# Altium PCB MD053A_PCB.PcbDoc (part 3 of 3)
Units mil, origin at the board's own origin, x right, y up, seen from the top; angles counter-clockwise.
Board outline 3650 x 5180 mil, 4 copper layers (Top Layer, GND Layer, Power Layer, Bottom Layer), stack 58.4 mil thick; 251 components, 138 nets, 532 pads, 1017 vias.
Unrouted connection lines stored in the file: 42.
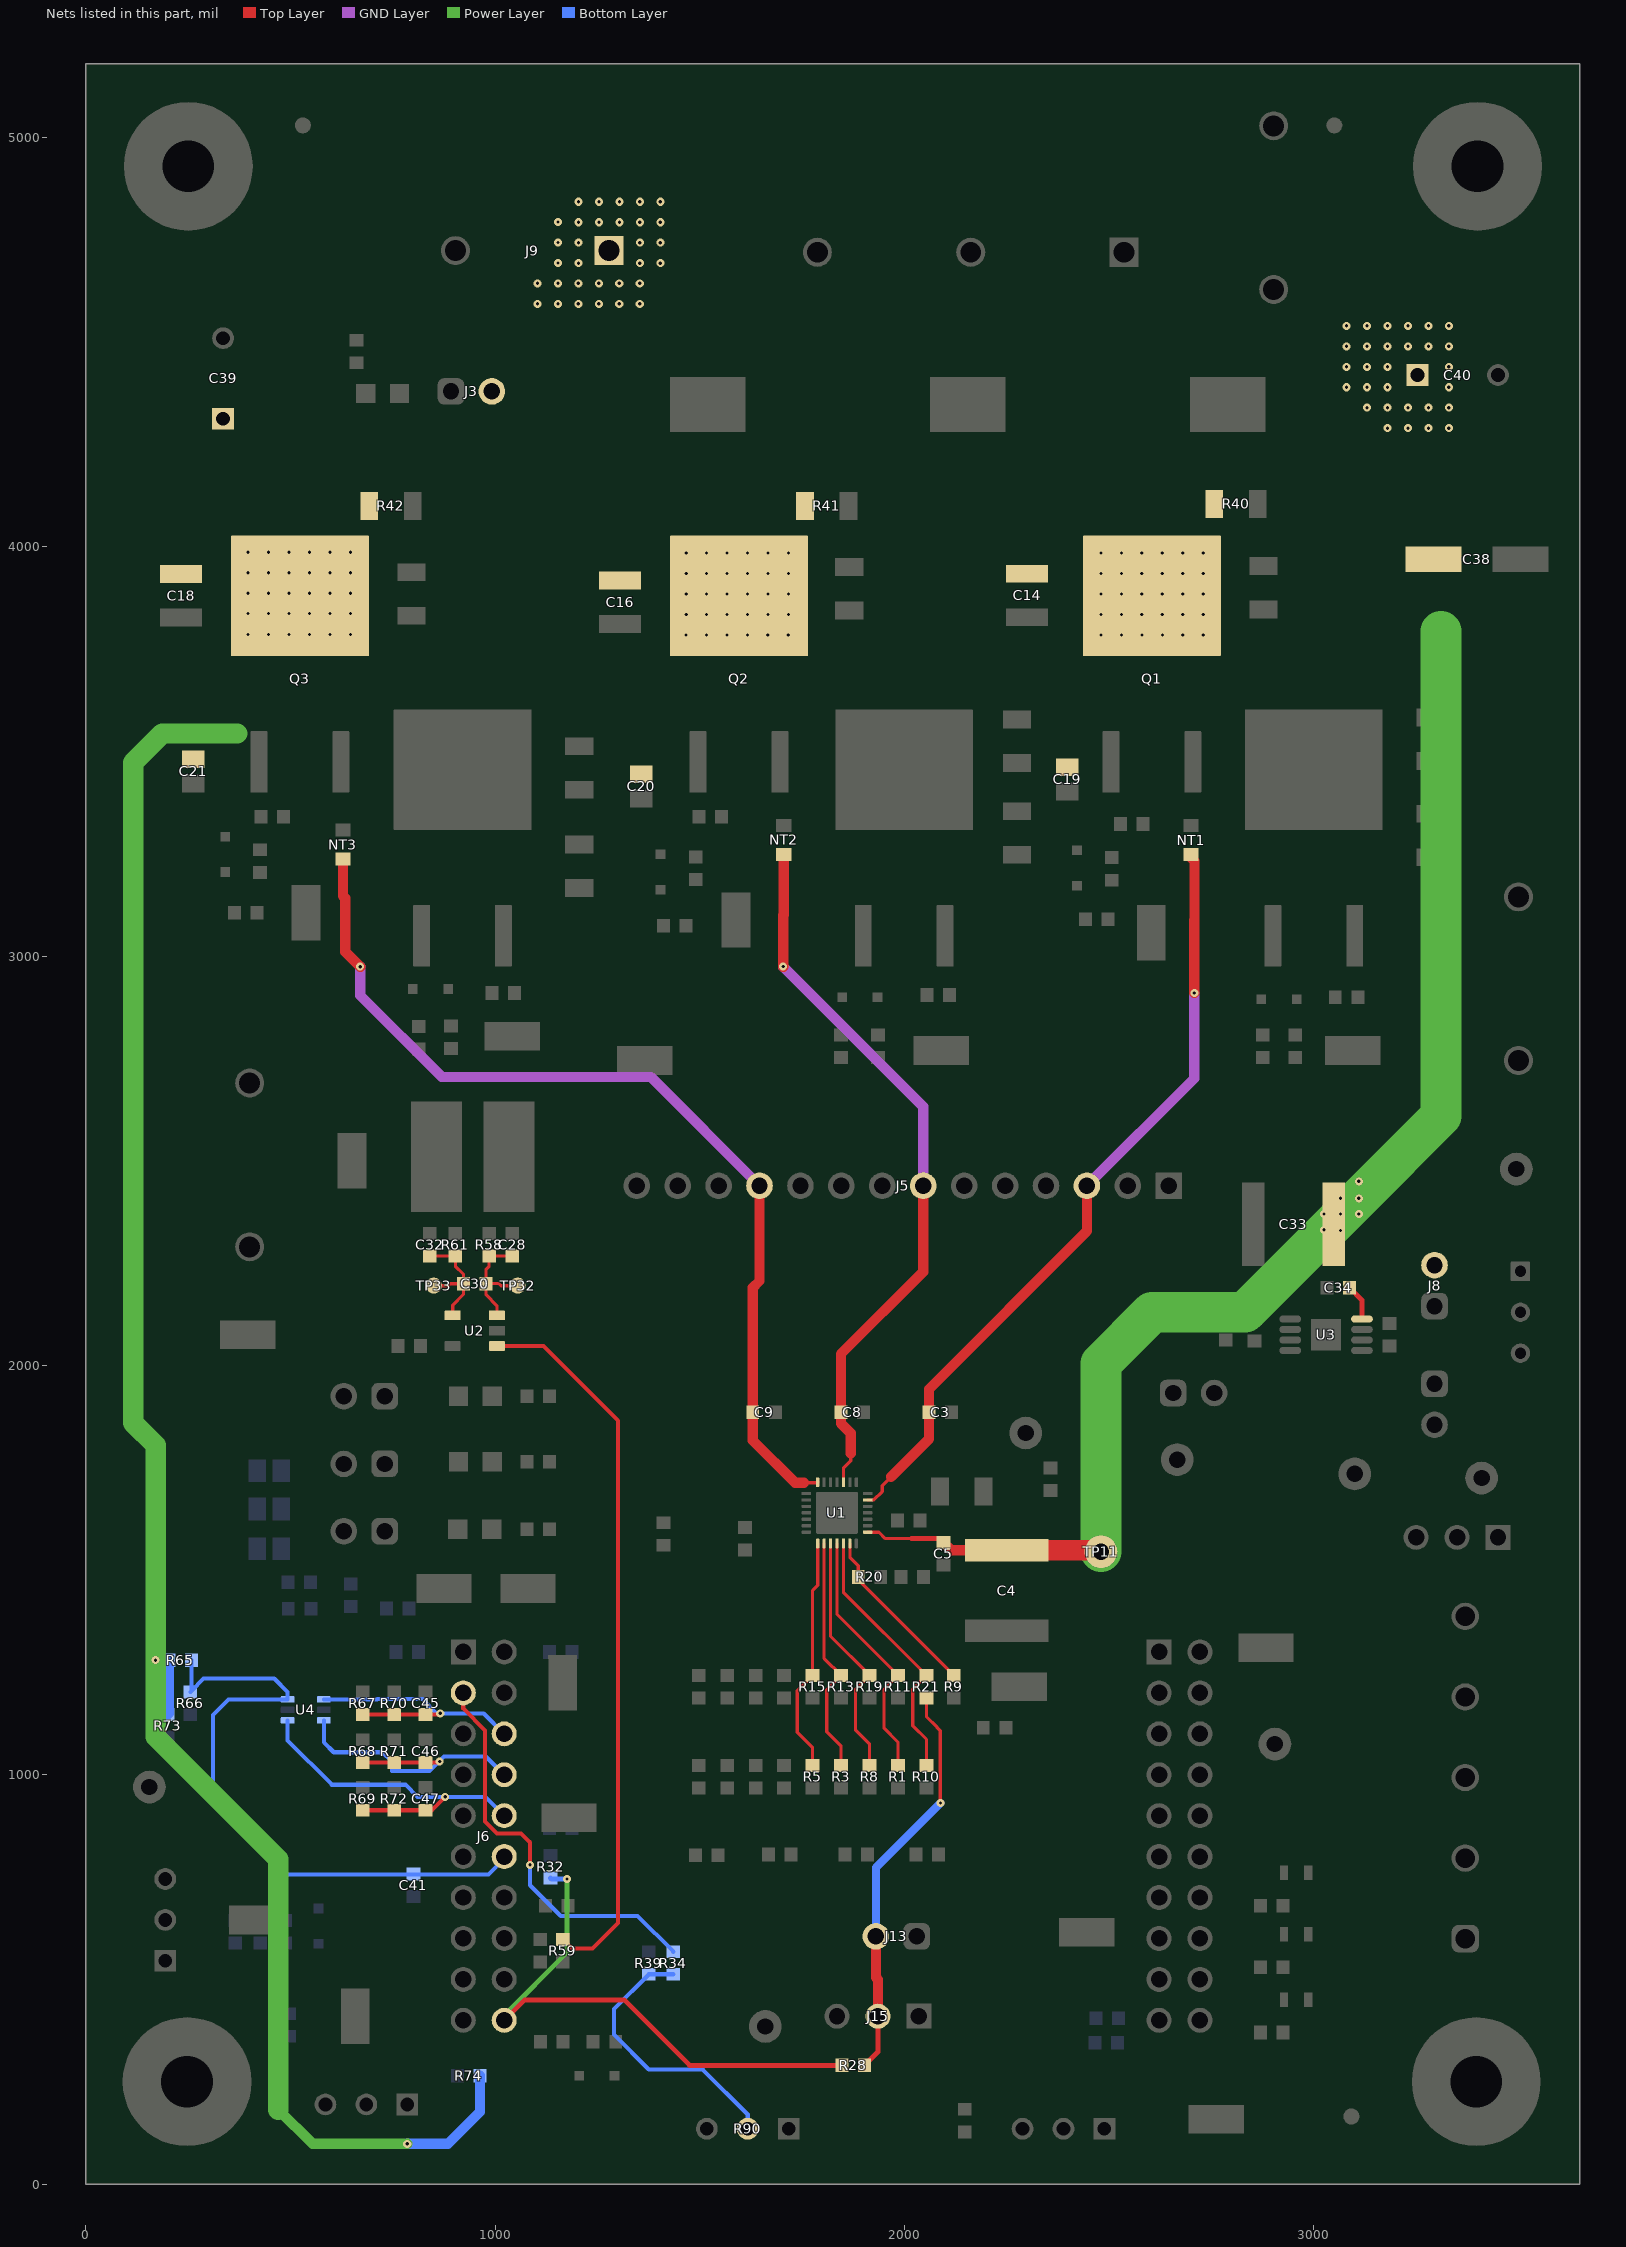
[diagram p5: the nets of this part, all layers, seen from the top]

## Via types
v1: diameter 20, hole 10, Top Layer to Bottom Layer, tented both sides, 759 vias
v2: diameter 19.68, hole 7.87, Top Layer to Bottom Layer, tented both sides, 248 vias
v3: diameter 19.68, hole 7.87, Top Layer to Bottom Layer, 10 vias

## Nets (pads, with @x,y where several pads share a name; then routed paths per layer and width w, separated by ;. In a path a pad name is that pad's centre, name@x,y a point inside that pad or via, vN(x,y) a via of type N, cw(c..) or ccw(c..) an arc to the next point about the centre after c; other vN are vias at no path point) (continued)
P22: R5.2 R15.2 U1.22 | length 578.9
  Top Layer w8: R5.2@1775.29,1022.56 1775.29,1066.21 1737.76,1103.74 1737.76,1205.03 R15.2@1775.29,1242.56 1775.29,1450.29 1787.76,1462.76 U1.22@1787.76,1565.2
P23: R3.2 R13.2 U1.23 | length 588.7
  Top Layer w8: U1.23@1803.5,1565.2 1803.5,1283.93 R13.2@1844.88,1242.56 1810,1207.68 1810,1105 1844.88,1070.12 R3.2@1844.88,1022.56
P24: R8.2 R19.2 U1.24 | length 610.6
  Top Layer w8: U1.24@1819.25,1565.2 1819.25,1337.77 R19.2@1914.47,1242.56 1880,1208.09 1880,1109.47 1914.47,1075 R8.2@1914.47,1022.56
P25: R1.2 R11.2 U1.25 | length 632.6
  Top Layer w8: U1.25@1835,1565.2 1835,1391.61 R11.2@1984.06,1242.56 1950,1208.5 1950,1113.74 1984.06,1079.68 R1.2@1984.06,1022.56
P26: R10.2 R21.2 U1.26 | length 654.6
  Top Layer w8: U1.26@1850.75,1565.2 1850.75,1445.46 R21.2@2053.65,1242.56 2020,1208.91 2020,1120 2053.65,1086.35 R10.2@2053.65,1022.56
P27: R9.2 R20.2 U1.27 | length 425.8
  Top Layer w8: U1.27@1866.5,1565.2 1866.5,1531.42 1886.91,1511.01 R20.2@1886.91,1483.21 ; R20.2@1883.38,1479.68 R9.2@2120.5,1242.56
POT: R34.1 R39.1 R90.2 | length 685.3
  Bottom Layer w10: R34.1@1435,512.44 R39.1@1375,512.44 1290,427.44 1290,365 1375,280 1506.87,280 1616.93,169.94 R90.2@1616.93,135
POT_MCU/NC_49C: J6.3 R34.2 | length 989.7
  Top Layer w10: J6.3@921.85,1200 921.85,1161.36 975,1108.21 975,885.49 1003.88,856.61 1063.39,856.61 1085,835 v2(1085,780)
  Bottom Layer w10: v2(1085,780) 1085,730 1160,655 1347.56,655 R34.2@1435,567.56
PVDD: C4.1 C5.1 C14.1 C16.1 C18.1 C19.1 C20.1 C21.1 C33.1 C34.1 C38.1 C39.1 C40.1 J3.2 J8.2 J9.1 Q1.4 Q2.4 Q3.4 R40.1 R41.1 R42.1 R65.2 R73.2 R74.2 TP11.1 U1.1 U3.8 | length 7936.5
  Top Layer w7.87: U1.1@1909.8,1592.76 1937.66,1592.76 1953.41,1577.01 2017.27,1577.01
  Top Layer w12: 2017.27,1576.98 2085.58,1576.98 C5.1@2095,1567.56 ; C34.1@3087.56,2190 3117.6,2159.96 U3.8@3117.6,2113.39
  Top Layer w25: C5.1@2095,1567.56 2114.13,1548.43 C4.1@2250,1548.43
  Top Layer w50: C4.1@2250,1548.43 2476.57,1548.43 TP11.1@2480,1545
  Power Layer w25: 470,181.77 553.66,98.11 v2(785,98.11)
  Power Layer w50: v2(170,1280) 170,1093.15 470,793.15 470,181.77 ; v2@170,1285 170,1805 115,1860 115,3473.01 186.12,3544.13 369.85,3544.13
  Power Layer w100: TP11.1@2480,1545 2480,2005 2605,2130 2831.5,2130 v2(3110,2408.5) 3310.96,2609.47 3310.96,3793.98
  Bottom Layer w25: v2(170,1280) R65.2@202.44,1280 202.44,1150 R73.2@200,1147.56 ; v2(785,98.11) 884.66,98.11 962.56,176 R74.2@962.56,264.71
  other v2: 3065,2330 3025,2331.47 3025,2370 3065,2370 3110,2370 3065,2408.5 3110,2450 1466,3785 1516,3785 1566,3785 1616,3785 1666,3785 1716,3785 2480,3785 2530,3785 2580,3785 2630,3785 2680,3785 2730,3785 396,3786 446,3786 496,3786 546,3786 596,3786 646,3786 1466.43,3834.85 1516.43,3834.85 1566.43,3834.85 1616.43,3834.85 1666.43,3834.85 1716.43,3834.85 2479.88,3834.96 2529.88,3834.96 2579.88,3834.96 2629.88,3834.96 2679.88,3834.96 2729.88,3834.96 396.2,3837.09 446.2,3837.09 496.2,3837.09 546.2,3837.09 596.2,3837.09 646.2,3837.09 1466.43,3884.85 1516.43,3884.85 1566.43,3884.85 1616.43,3884.85 1666.43,3884.85 1716.43,3884.85 2479.88,3884.96 2529.88,3884.96 2579.88,3884.96 2629.88,3884.96 2679.88,3884.96 2729.88,3884.96 396.2,3887.09 446.2,3887.09 496.2,3887.09 546.2,3887.09 596.2,3887.09 646.2,3887.09 1466.43,3934.85 1516.43,3934.85 1566.43,3934.85 1616.43,3934.85 1666.43,3934.85 1716.43,3934.85 2479.88,3934.96 2529.88,3934.96 2579.88,3934.96 2629.88,3934.96 2679.88,3934.96 2729.88,3934.96 396.2,3937.09 446.2,3937.09 496.2,3937.09 546.2,3937.09 596.2,3937.09 646.2,3937.09 1466.43,3984.85 1516.43,3984.85 1566.43,3984.85 1616.43,3984.85 1666.43,3984.85 1716.43,3984.85 2479.88,3984.96 2529.88,3984.96 2579.88,3984.96 2629.88,3984.96 2679.88,3984.96 2729.88,3984.96 396.2,3987.09 446.2,3987.09 496.2,3987.09 546.2,3987.09 596.2,3987.09 646.2,3987.09 3180,4290.14 3230,4290.14 3280,4290.14 3330,4290.14 3130,4340.14 3180,4340.14 3230,4340.14 3280,4340.14 3330,4340.14 3080,4390.14 3130,4390.14 3180,4390.14 3330,4390.14 3080,4440.14 3130,4440.14 3180,4440.14 3330,4440.14 3080,4490.14 3130,4490.14 3180,4490.14 3230,4490.14 3280,4490.14 3330,4490.14 3080,4540.14 3130,4540.14 3180,4540.14 3230,4540.14 3280,4540.14 3330,4540.14 1103,4594 1153,4594 1203,4594 1253,4594 1303,4594 1353,4594 1103,4644 1153,4644 1203,4644 1253,4644 1303,4644 1353,4644 1203.24,4693.35 1353.24,4693.35 1403.24,4693.35 1153,4694 1203.24,4743.35 1353.24,4743.35 1403.24,4743.35 1153,4744 1203.24,4793.35 1253.24,4793.35 1303.24,4793.35 1353.24,4793.35 1403.24,4793.35 1153,4794 1203.24,4843.35 1253.24,4843.35 1303.24,4843.35 1353.24,4843.35 1403.24,4843.35
SHA: C3.2 J5.3 NT1.1 U1.6 | length 1912.5
  Top Layer w7.87: U1.6@1909.8,1671.5 1925.23,1671.5 1945.67,1691.94 1945.67,1706.48 1967.1,1727.9
  Top Layer w25: 1967.1,1727.9 2060,1820.8 C3.2@2060,1885.43 2060,1942.63 2445.67,2328.3 J5.3@2445.67,2438.91 ; NT1.1@2700,3240.63 2708.5,3232.13 2708.5,3088.66 2708,3088.16 v2(2708,2910)
  GND Layer w25: J5.3@2445.67,2438.91 2708,2701.24 v2(2708,2910)
SHB: C8.2 J5.7 NT2.1 U1.10 | length 1772.3
  Top Layer w7.87: U1.10@1850.75,1714.8 1850.75,1749.06 1868.46,1766.77 1868.46,1785
  Top Layer w25: v2(1703.5,2974.5) 1703.5,3100 1704.76,3101.26 NT2.1@1704.76,3244.33 ; 1868.46,1785 1868.46,1834.67 1844.6,1858.53 C8.2@1844.6,1885.43 1844.6,2027.9 2045.67,2228.97 J5.7@2045.67,2438.91
  GND Layer w25: v2(1703.5,2974.5) 2045.67,2632.33 J5.7@2045.67,2438.91
SHC: C9.2 J5.11 NT3.1 U1.14 | length 2345
  Top Layer w7.87: 1754.29,1713.33 1786.28,1713.33 U1.14@1787.76,1714.8
  Top Layer w25: NT3.1@627.77,3232.52 627.77,3147.31 633.5,3141.57 633.5,3010.96 v2(670,2974.47) ; C9.2@1629.2,1885 1629.2,1816.79 1732.67,1713.33 1754.29,1713.33 ; C9.2@1629.2,1885.43 1629.2,2190 1645.67,2206.47 J5.11@1645.67,2438.91
  GND Layer w25: v2(670,2974.47) 670,2903.85 868.85,2705 1379.58,2705 J5.11@1645.67,2438.91
SN: C30.2 C32.1 R61.1 TP33.1 U2.4 | length 301.4
  Top Layer w8: C32.1@840,2267.44 R61.1@902.6,2267.44 902.6,2242.4 922.44,2222.56 C30.2@922.44,2200 ; TP33.1@850,2195 885,2195 890,2200 C30.2@922.44,2200 ; U2.4@895.87,2122.4 895.87,2147.2 922.44,2173.78 C30.2@922.44,2200
SOA: R59.2 U2.1 | length 1769.2
  Top Layer w10: U2.1@1004.13,2047.6 1117.4,2047.6 1300,1865 1300,637.6 1237.4,575 1187.56,575 R59.2@1165,597.56
SP: C28.2 C30.1 R58.1 TP32.1 U2.3 | length 294.9
  Top Layer w7.87: U2.3@1004.13,2122.4 1004.13,2145.87 977.56,2172.44 C30.1@977.56,2200 ; C28.2@1041.38,2267.44 R58.1@985,2267.44 985,2242.44 977.56,2235 C30.1@977.56,2200 ; TP32.1@1054.88,2195 1014.18,2195 1009.18,2200 C30.1@977.56,2200
VDSLVL: J13.2 J15.2 R21.1 R28.2 | length 992.4
  Top Layer w8: R21.1@2053.65,1187.44 2053.65,1141.89 2080,1115.53 2080,1115 2087.56,1107.44 v2(2087.56,930.98)
  Top Layer w12: R28.2@1902.31,290 1935,322.69 J15.2@1935,410
  Top Layer w25: J13.2@1930,605 1930,505 1935,500 J15.2@1935,410
  Bottom Layer w20: J13.2@1930,605 1930,773.42 v2(2087.56,930.98)
VDSLVL/C_TAP: J6.20 R28.1 R32.1 | length 1361.8
  Top Layer w12: J6.20@1021.85,400 1071.85,450 1315,450 1475,290 R28.1@1847.19,290
  Power Layer w12: J6.20@1021.85,400 1021.85,411.85 1175,565 v2(1175,745)
  Bottom Layer w12: R32.1@1135,747.44 1137.44,745 v2(1175,745)
VSENA: C45.2 J6.6 R67.1 R70.2 U4.1 | length 666.7
  Top Layer w10: R67.1@676.39,1147.44 R70.2@753.08,1147.44 C45.2@829.77,1147.44 862.98,1147.44 v2(865.54,1150)
  Bottom Layer w10: U4.1@581.14,1184.09 711.74,1184.09 712.65,1185 821.91,1185 856.91,1150 v2@865,1150 ; v2@865,1150.54 v2(865.54,1150) 971.85,1150 J6.6@1021.85,1100
VSENB: C46.1 J6.8 R68.1 R71.2 U4.3 | length 759.5
  Top Layer w10: R68.1@676.39,1030.37 R71.2@753.08,1030.37 C46.1@829.77,1030.37 862.13,1030.37 v2(864.2,1032.44)
  Bottom Layer w10: U4.3@581.14,1132.91 581.14,1079.28 605.42,1055 725,1055 747.41,1032.59 747.41,1009 839,1009 v2@863.32,1033.32 ; v2(864.2,1032.44) v2@866.76,1035 ; v2@865.88,1035.88 875,1045 976.77,1045 1021.77,1000 J6.8@1021.85,1000
VSENC: C47.1 J6.10 R69.1 R72.2 U4.4 | length 869.4
  Top Layer w10: R69.1@676.39,913.3 R72.2@753.08,913.3 C47.1@829.77,913.3 844.93,913.3 v2(877.6,945.97)
  Bottom Layer w10: U4.4@492.56,1132.91 492.56,1083.64 600.59,975.61 780.24,975.61 809.85,946 975.85,946 J6.10@1021.85,900
VSENPVDD: C41.1 J6.12 R65.1 R66.2 U4.6 | length 1576.3
  Bottom Layer w10: R66.2@255,1202.56 R66.2@257.56,1205.12 ; R65.1@257.56,1280 R66.2@257.56,1205.12 ; J6.12@1021.85,800 1021.85,795.08 983.39,756.61 483.39,756.61 310,930 310,1145.52 348.58,1184.09 U4.6@492.56,1184.09 492.56,1202.44 460,1235 287.44,1235 R66.2@257.56,1205.12
pads on no net: FID1.1 FID2.1 FID3.1 H5.0 H6.0 H7.0 H8.0 LBL1.0 SH-J1.0 SH-J2.0 SH-J3.0 SH-J4.0 SH-J5.0 SH-J6.0 SH-J7.0 SH-J8.0 SH-J9.0

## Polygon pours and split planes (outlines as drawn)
GVDD on Top Layer "TOP_LAYER_GVDD_P124" (solid, remove dead copper, pour order 124): 2079.4,1760.22 2111.75,1760.22 2246.54,1895 2375,1895 2375,1726.8 2373.2,1725 2369.08,1729.12 2140,1729.12 2140,1655.75 1962.16,1648.98
PVDD on Top Layer "TOP_LAYER_PVDD_P128" (solid, remove dead copper, pour order 128): 3005,2515 3005,2225 3057.17,2225 3057.17,2125 3080,2125 3080,2102.56 3150,2102.56 3150,2190 3345,2190 3345,2515
GND on Top Layer "TOP_LAYER_GND_P157" (solid, remove dead copper, pour order 157): 24.84,5196.95 3674.84,5196.95 3674.84,16.95 24.84,16.95
AVDD on Top Layer "TOP_LAYER_AVDD_P145" (solid, remove dead copper, pour order 145): 1701.22,1905 1365,1905 1342.2,1882.2 1342.2,1777.53 1354.73,1765 1605.25,1765 1605.25,1830.55 1683.62,1830.55 1725.32,1872.25 1701.22,1896.35
PVDD on Top Layer "TOP_LAYER_PVDD_P144" (solid, remove dead copper, pour order 144): 2890,4565 3356.77,4565 3375,4546.77 3375,3690.23 3345,3680.72 3150,3680.72 3150,4170 2890,4430
LSS on Top Layer "TOP_LAYER_LSS_P141" (solid, remove dead copper, pour order 141): 930,3430 3331.96,3430 3405,3356.96 3405,3171.26 3310,3076.26 3310,2477.55 1412.92,2477.55 1395.1,2355 1284,2355 1240,2355 1110,2355 1090,2375 970,2375 970,2920.47 680.94,3135 680,3244.68 970,3361.8
GLA_FET on Top Layer "TOP_LAYER_GLA_FET_P139" (solid, remove dead copper, pour order 139): 2875,3130 2922.73,3130 2927.73,3125 2935.94,2950 3060.5,2940 3080,2920.5 3080,2780 2920,2780 2915,2785 2915,2919.83 2875,2959.83
GLB_FET on Top Layer "TOP_LAYER_GLB_FET_P138" (solid, remove dead copper, pour order 138): 1868.41,3132.12 1919.81,3132.12 1926.42,3125.51 1926.42,2981.32 1975.47,2932.27 2078.23,2932.27 2085,2925.5 2085,2775 2065,2755 2040,2780 1890,2780 1890,2950 1868.31,2950
GLC_FET on Top Layer "TOP_LAYER_GLC_FET_P137" (solid, remove dead copper, pour order 137): 790,3133.59 791.47,3132.12 855,3132.12 855,2990 907.42,2937.58 1024.72,2937.58 1024.72,2870.28 1067.44,2827.56 1068.11,2740 979.89,2740 850,2740 850,2915.33 815,2950.33 790,2950.33
GHA_FET on Top Layer "TOP_LAYER_GHA_FET_P136" (solid, remove dead copper, pour order 136): 2445,3561.47 2575,3561.47 2575,3377.97 2555,3357.97 2555,3251.8 2635,3171.8 2635,3035 2564.4,3035 2564.4,3168.55 2522.95,3210 2409.59,3210 2409.59,3296.92 2445,3332.33
GHB_FET on Top Layer "TOP_LAYER_GHB_FET_P135" (solid, remove dead copper, pour order 135): 1445,3563.13 1447.66,3565.78 1565,3565.78 1565,3385 1522.44,3385 1525,3382.44 1525,3284.98 1625,3184.98 1625,3052.68 1617.32,3045 1533.11,3045 1530,3048.11 1530,3216.78 1526.78,3220 1380,3220 1380,3282.42 1445,3347.42
GHC_FET on Top Layer "TOP_LAYER_GHC_FET_P134" (solid, remove dead copper, pour order 134): 350,3565.78 350,3361.95 323.38,3335.33 323.38,3237.91 459.69,3237.91 467.6,3230 467.6,3080.51 500,3048.11 572.34,3048.11 572.34,3224.36 457.72,3338.98 457.72,3565.78
GND on Top Layer "TOP_LAYER_GND_P133" (solid, remove dead copper, pour order 133): 1169,3904.41 1434.08,3904.41 1437.58,3900.91 1437.58,3575.12 1173.88,3575.12 1169,3580
GND on Top Layer "TOP_LAYER_GND_P132" (solid, remove dead copper, pour order 132): 2184.35,3914.49 2443.8,3914.49 2462.2,3896.09 2462.2,3619.49 2459.53,3622.17 2184.35,3622.17
PVDD on Top Layer "TOP_LAYER_PVDD_P131" (solid, remove dead copper, pour order 131): 2803.49,3682.2 2803.49,4136.78 2725.26,4215 2291.73,4215 2291.73,4103.85 2244.09,4056.21 2235,4056.21 2235,3919.41 2250,3904.41 2422.56,3904.41 2435.08,3891.89 2435.08,3622.17 2350,3537.09 2350,3446.49 2360.98,3435.51 2437.68,3435.51 2450,3447.83 2450,3537.09 2564.4,3580 2592.91,3680 2602.4,3680
PVDD on Top Layer "TOP_LAYER_PVDD_P130" (solid, remove dead copper, pour order 130): 1775.57,3655 1775.57,4023.9 1806.68,4055 1803.68,4058 1801.38,4058 1801.38,4132.76 1848.62,4180 1893.74,4180 1892.29,4215 1489.15,4215 1341.24,4055 1287.6,4055 1225,3992.4 1225,3880.2 1400.43,3880.2 1411.06,3869.57 1411.06,3665.2 1411.06,3647.14 1382.58,3574.19 1300,3517.09 1300,3411.65 1421.26,3415.15 1559.71,3655
PVDD on Top Layer "TOP_LAYER_PVDD_P129" (solid, remove dead copper, pour order 129): 710.13,4006.54 747.36,4043.77 747.36,4170.44 1015.44,4170.44 1450,4605 1450,4842.44 1412.44,4880 1174.2,4880 1124.2,4830 1124.2,4829.2 1100,4805 1100,4700 855,4455 611,4455 561,4426.57 539.43,4426.57 301.85,4426.57 150.67,4275.39 150.67,3905 313.11,3905 313.11,3652.43 207.48,3585.59 207.48,3467.91 325.15,3467.91 653.18,3652.43 710.13,3709.38
OUTA on Top Layer "TOP_LAYER_OUTA_P127" (solid, remove dead copper, pour order 127): 2762.91,3283.5 2560,3283.5 2560,3376.97 2602.4,3419.37 2602.4,3645.17 2612.46,3655.23 2816.93,3655.23 2816.93,3891.89 2830.04,3905 2917.56,3905 2917.56,4145.16 2882.72,4180 2787.91,4180 2758.75,4218.66 2626.5,4218.66 2381.1,4489.1 2381.1,4880 2656.8,4880 2760.94,4775.85 2760.94,4614.69 3175,4200.63 3175,3682.2 3224.2,3633 3375,3633 3375,3555 3350,3530 3199.98,3530 3199.98,3234.88 3170.1,3205 2762.91,3205
OUTB on Top Layer "TOP_LAYER_OUTB_P126" (solid, remove dead copper, pour order 126): 1550,3292.2 1535,3292.2 1535,3367.94 1556.8,3377.42 1556.8,3619.49 1806.68,3619.49 1806.68,3878.8 1832.87,3905 1929.13,3905 1890.66,4230.2 1680,4230.2 1899.05,4455 1982.81,4538.76 1988.23,4880 2315,4880 2365,4880 2365,4488.16 2615.89,4220 2319.31,4220 2315,4156.04 2211.32,4052.36 2211.32,3649.5 2325,3649.5 2322.64,3647.14 2322.64,3519.49 2201.02,3519.49 2201.02,3263.6 2156.8,3219.37 1778.58,3219.37 1778.58,3283.5 1769.88,3292.2 1561.52,3292.2 1556.8,3292.2
OUTC on Top Layer "TOP_LAYER_OUTC_P125" (solid, remove dead copper, pour order 125): 465.1,3540.65 579.45,3655 747.36,3655 747.36,3869.57 736.93,3880 868.48,3880.2 868.48,4155 1006.9,4161.5 1745.5,4880 1960.31,4880 1964.76,4634.76 1964.76,4505 1690,4229.32 1575,4229.32 1410,4080 1275,4080 1200,4005 1200,3630 1265.99,3564.01 1265.99,3467.91 1137.91,3467.91 1121.97,3451.97 1121.97,3255 703.72,3255 683.31,3275.42 519.33,3275.42 465.1,3329.65
LSS on Power Layer "POWER_LAYER_LSS_P140" (solid, remove dead copper, pour order 140): 930,3430 3331.96,3430 3405,3356.96 3405,3171.26 3310,3076.26 3310,2477.55 1412.92,2477.55 1395.1,2355 1284,2355 1240,2355 1110,2355 1090,2375 970,2375 970,2920.47 680.94,3135 680,3244.68 970,3361.8
GND on Power Layer "POWER_LAYER_GND_P165" (solid, remove dead copper, pour order 165): 0,5180 3650,5180 3650,0 0,0
AVDD on Power Layer "POWER_LAYER_AVDD_P153" (solid, remove dead copper, pour order 153): 1702.02,1904.76 1365.8,1904.76 1343,1881.96 1343,1777.29 1355.53,1764.76 1565,1764.76 1635,1830.31 1684.42,1830.31 1726.12,1872.01 1702.02,1896.11
PVDD on Power Layer "POWER_LAYER_PVDD_P149" (solid, remove dead copper, pour order 149): 1412.44,4880 1450,4842.44 1450,4628.1 1051.9,4230 3192,4230 2890,4521.68 2890,4565 3385.61,4565 3387.09,4563.52 3386,4218 3386,3275.5 3277.16,3166.66 416.21,3166.66 313.11,3269.76 313.11,3905 150.67,3905 150.67,4275.39 301.85,4426.57 561,4426.57 589.42,4455 855,4455 1100,4700 1100,4805.8 1174.2,4880
OUTA on Power Layer "POWER_LAYER_OUTA_P148" (solid, remove dead copper, pour order 148): 3174.36,4185 2786.28,4185 2757.11,4223.66 2624.86,4223.66 2379.47,4494.1 2379.47,4885 2655.16,4885 2759.31,4780.85 2759.31,4619.69 3174.36,4227.33
OUTB on Power Layer "POWER_LAYER_OUTB_P147" (solid, remove dead copper, pour order 147): 2319,4230.2 1680,4230.2 1899.05,4455 1982.81,4538.76 1988.23,4880 2315,4880 2365,4880 2365,4488.16 2604,4230.2
OUTC on Power Layer "POWER_LAYER_OUTC_P146" (solid, remove dead copper, pour order 146): 1077.62,4231.84 1746.12,4881.84 1965.38,4880 1965.38,4636.6 1965.38,4506.84 1690.62,4231.16
LSS on GND Layer "GND_LAYER_LSS_P158" (solid, remove dead copper, pour order 158): 930,3430 3331.96,3430 3405,3356.96 3405,3171.26 3310,3076.26 3310,2477.55 1412.92,2477.55 1395.1,2355 1284,2355 1240,2355 1110,2355 1090,2375 970,2375 970,2920.47 680.94,3135 680,3244.68 970,3361.8
GND on GND Layer "GND_LAYER_GND_P159" (solid, remove dead copper, pour order 159): 0,5180 3650,5180 3650,0 0,0
OUTA on GND Layer "GND_LAYER_OUTA_P152" (solid, remove dead copper, pour order 152): 3208.31,4184.48 2800.59,4184.48 2771.43,4223.14 2639.17,4223.14 2393.78,4493.58 2393.78,4884.48 2669.47,4884.48 2773.62,4780.33 2773.62,4619.17
OUTB on GND Layer "GND_LAYER_OUTB_P151" (solid, remove dead copper, pour order 151): 2319,4230.2 1680,4230.2 1899.05,4455 1982.81,4538.76 1988.23,4880 2315,4880 2365,4880 2365,4488.16 2604,4230.2
OUTC on GND Layer "GND_LAYER_OUTC_P150" (solid, remove dead copper, pour order 150): 1081.11,4231.82 1749.61,4881.82 1968.87,4879.99 1968.87,4636.59 1968.87,4506.82 1694.11,4231.15
LSS on Bottom Layer "BOTTOM_LAYER_LSS_P143" (solid, remove dead copper, pour order 143): 930,3430 3331.96,3430 3405,3356.96 3405,3171.26 3310,3076.26 3310,2477.55 1412.92,2477.55 1395.1,2355 1284,2355 1240,2355 1110,2355 1090,2375 970,2375 970,2920.47 680.94,3135 680,3244.68 970,3361.8
OUTA on Bottom Layer "BOTTOM_LAYER_OUTA_P156" (solid, remove dead copper, pour order 156): 3208.31,4180 2800.59,4180 2771.43,4218.66 2639.17,4218.66 2393.78,4489.1 2393.78,4880 2669.47,4880 2773.62,4775.85 2773.62,4614.69
OUTB on Bottom Layer "BOTTOM_LAYER_OUTB_P155" (solid, remove dead copper, pour order 155): 2325,4225 1686,4225 1905.06,4449.8 1988.81,4533.55 1994.23,4874.8 2321,4874.8 2371,4874.8 2371,4482.95 2610,4225
OUTC on Bottom Layer "BOTTOM_LAYER_OUTC_P154" (solid, remove dead copper, pour order 154): 1081.11,4231.82 1749.61,4881.82 1968.87,4879.99 1968.87,4636.59 1968.87,4506.82 1694.11,4231.15
GND on Bottom Layer "BOTTOM_LAYER_GND_P167" (solid, remove dead copper, pour order 167): 0,5180 3650,5180 3650,0 0,0

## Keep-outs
Keep-Out Layer:
  text ".Layer_Name" at 577,-428.49 h60

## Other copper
Top Layer:
  pour cut-out: 856.42,2525 959.8,2525 959.8,2222.56 930,2222.56 930,2293.91 872.83,2293.34 872.83,2348.31 872.83,2375 856.42,2375

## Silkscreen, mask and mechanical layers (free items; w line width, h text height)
Top Overlay:
  lines w8: 314,776 330,792 ; 316,472 334,454 ; 330,733 330,792 ; 334,513 334,454 ; 346,776 330,792 ; 351,471 334,454 ; 515,380 495,360 ; 516,339 495,360 ; 571,360 495,360 ; 747,369 819,369 800,388 ; 800,352 818,370
  lines w10: 1462.65,1060 2090,1060 2090,1270 ; 2204,1596 2205,1595 ; 2204,1596 2205,1595 ; 2204,1596 2204,1925 1570,1925 1570,1456.48 2120.5,1456.48 2120.5,1310 2371.66,1310 2371.66,1595 2355,1595 2205,1595 ; 1462.65,850 1462.65,1270 2155,1270 2155,850 1462.65,850
  text "GND" at 833.69,4455 h40
  text "PVDD" at 1200,4455 h40
  text "OUTC" at 1711.59,4454.45 h40
  text "OUTB" at 2084.79,4454.45 h40
  text "OUTA" at 2458,4454.45 h40
  text "LSS" at 1344.97,2511.91 h30 r45
  text "GLC" at 1438.97,2509.91 h30 r45
  text "SHC" at 1638.97,2506.91 h30 r45
  text "GHC" at 1536.97,2503.91 h30 r45
  text "BSTC" at 1744.97,2503.91 h30 r45
  text "GLB" at 1857.97,2503.91 h30 r45
  text "GHB" at 1952.97,2503.91 h30 r45
  text "SHB" at 2053.97,2503.91 h30 r45
  text "BSTB" at 2149.97,2503.91 h30 r45
  text "GLA" at 2258.97,2503.91 h30 r45
  text "GHA" at 2368.97,2503.91 h30 r45
  text "SHA" at 2469.97,2503.91 h30 r45
  text "BSTA" at 2562.97,2503.91 h30 r45
  text "GND" at 2669.97,2503.91 h30 r45
  text "LDO_" at 3235,2365 h30
  text "EN" at 3256.86,2320 h30
  text "DRV8328A/B/C/D" at 1648.36,1945 h35
  text "AVDD" at 445,1889.57 h30
  text "DT" at 3479.33,1875.99 h30
  text "DT_POT" at 3042.76,1870 h30
  text "EXT_" at 3475,1765 h30
  text "HALL_" at 3175,1735 h30
  text "nFAULT" at 382.01,1726 h30
  text "HALL_" at 3475,1720 h30
  text "PWR" at 3175,1695 h30
  text "PWR" at 3475,1677.56 h30
  text "HALL_PWR_" at 2829.03,1605 h30
  text "MCU_LED" at 342.73,1560.1 h30
  text "SEL" at 3010,1545 h30
  text "EXT" at 3560,1540 h30 r90
  text "AVDD" at 3172.2,1525 h30 r90
  text "AVDD cap" at 1311.03,1496.81 h25
  text "(for C/D)" at 1308.48,1457.2 h25
  text "HALL" at 2997.79,1420 h35
  text "A/B" at 1874.37,1415 h30
  text "DT" at 1993.06,1370 h30
  text "PWR" at 3032.2,1365 h35
  text "HALLA" at 2961.09,1180 h35
  text "DRV8328AEVM" at 173.27,1121.81 h120 r90
  text "A/B" at 1435,1120 h30 r90
  text "'.PRJ_Number'.PCB_Rev" at 291.7,1111.24 h108.27 r90
  text "HALLB" at 2966.09,977.2 h35
  text "C/D" at 1430,920 h30 r90
  text "HALLC" at 2966.54,796.3 h35
  text "SLEEP" at 396.2,735 h30 r90
  text "VDS_DIS" at 1879.36,673.51 h30
  text "GND" at 3030.31,535 h35
  text "DRV" at 733,442 h30
  text "DRV" at 497,440 h30
  text "WAKE" at 403.97,430 h30 r90
  text "VDS_EXT" at 1395,400.99 h30
  text "OFF" at 496,396 h30
  text "ON" at 734,396 h30
  text "POT" at 2143.46,370.67 h30 r90
  text "EXT" at 1764.15,367.64 h30 r90
  text "VDSLVL" at 2302.65,255.57 h30
  text ".Layer_Name" at 577,-428.49 h60
Bottom Overlay:
  text ".Layer_Name" at 577,-428.49 h60
Top Paste:
  text ".Layer_Name" at 577,-428.49 h60
Bottom Paste:
  text ".Layer_Name" at 577,-428.49 h60
Top Solder:
  text ".Layer_Name" at 577,-428.49 h60
  text ".Layer_Name" at 577,-428.49 h60
Solder Side:
  text ".Layer_Name" at 577,-428.49 h60
Drill Guide:
  text ".Layer_Name" at 577,-428.49 h60
M1 Board Outline:
  the board outline again, w10
  text ".Layer_Name" at 577,-428.49 h60
M2 Board Dimensions:
  rectangle: 0,155 125,280
  rectangle: 125,30 500,155
  lines w7: 0,155 1000,155 ; 125,30 125,280 ; 250,30 250,280 ; 500,30 500,280 ; 750,30 750,280 ; 0,30 1000,30 1000,280 0,280 0,30
  text ".Layer_Name" at 577,-428.49 h60
M3 3D STEP Top:
  text ".Layer_Name" at 577,-428.49 h60
M4 3D STEP Bottom:
  text ".Layer_Name" at 577,-428.49 h60
M5 Assembly Top:
  lines w10: -292,-500.17 6308,-500.17 ; -292,-296.83 6310,-296.83 ; -292,-93.5 -292,-703.5 3713,-703.5 6310,-703.5 6310,-93.5 -291.5,-93.5 -291.5,-703.5 1284,-703.5 ; 2173,-703.5 2173,-93.5 ; 3440,-296.83 3440,-93.5 ; 4280,-296.83 4280,-93.5 ; 4902,-710 4902,-507.17
  text "COMPONENTS MARKED 'DNP' SHOULD NOT BE POPULATED." at 1153.5,111.5 h60
  text "ASSEMBLY VARIANT:" at 1153,-4 h60
  text ".VariantName" at 2189,-4 h60
  text "PCB VIEWED FROM TOP SIDE" at -228.5,-225.67 h60
  text "BOARD #:" at 2248,-225.67 h60
  text ".PRJ_Number" at 2793.5,-225.67 h60
  text "REV:" at 3638,-225.67 h60
  text ".PCB_Rev" at 3929.5,-225.67 h60
  text "SVN REV:" at 4476,-225.67 h60
  text ".VersionControl_RevNumber" at 4982,-225.67 h60
  text "TID #:" at 2248,-429 h60
  text ".TID" at 2793.5,-429 h60
  text "PLOT NAME =" at -228.5,-634.34 h60
  text ".plot_File_Name" at 577,-634.34 h60
  text "GENERATED    :" at 2250,-634.34 h60
  text ".Print_Date" at 3119.5,-634.34 h60
  text ".Print_Time" at 3848.5,-634.34 h60
  text "TEXAS INSTRUMENTS" at 5113,-634.34 h60
M6 Assembly Bottom:
  lines w10: -292.5,-297.33 6309.5,-297.33 ; -290.5,-500.67 6309.5,-500.67 ; 1115.5,-710.5 1115.5,-507.67 ; 1737.5,-297.33 1737.5,-94 ; 2577.5,-297.33 2577.5,-94 ; 3844.5,-704 3844.5,-94 ; 4733.5,-704 6309,-704 6309,-94 -292.5,-94 -292.5,-704 2304.5,-704 6309.5,-704 6309.5,-94
  text "COMPONENTS MARKED 'DNP' SHOULD NOT BE POPULATED." at 6102,112 h60
  text ".VariantName" at 5058,-4 h60
  text "ASSEMBLY VARIANT:" at 6097,-4 h60
  text ".VersionControl_RevNumber" at 1035.5,-226.17 h60
  text "SVN REV:" at 1541.5,-226.17 h60
  text ".PCB_Rev" at 2088,-226.17 h60
  text "REV:" at 2379.5,-226.17 h60
  text ".PRJ_Number" at 3224,-226.17 h60
  text "BOARD #:" at 3769.5,-226.17 h60
  text "PCB VIEWED FROM BOTTOM SIDE" at 6246,-226.17 h60
  text ".TID" at 3224,-429.5 h60
  text "TID #:" at 3769.5,-429.5 h60
  text "TEXAS INSTRUMENTS" at 904.5,-634.84 h60
  text ".Print_Time" at 2169,-634.84 h60
  text ".Print_Date" at 2898,-634.84 h60
  text "GENERATED    :" at 3767.5,-634.84 h60
  text ".plot_File_Name" at 5440.5,-634.84 h60
  text "PLOT NAME =" at 6246,-634.84 h60
M9 Title Sheet:
  drawing of 57 lines, arcs and shapes, not listed
  text "1" at 739.84,8466.5 h70
  text "2" at 3235.5,8466.5 h70
  text "3" at 5724.84,8466.5 h70
  text "4" at 8231.51,8466.5 h70
  text "5" at 10730.5,8466.5 h70
  text "6" at 13235.5,8466.5 h70
  text "A" at -416.5,7323.5 h70
  text "A" at 14383.5,7323.5 h70
  text "B" at -416.5,4943.5 h70
  text "B" at 14383.5,4943.5 h70
  text "C" at -416.5,2568.5 h70
  text "C" at 14383.5,2568.5 h70
  text "PROJECT TITLE:" at 11343.5,707.5 h45
  text ".PRJ_Title" at 11393.5,574.17 h70
  text "DESIGNED FOR:" at 11343.5,406.5 h45
  text ".PRJ_Customer" at 11393.5,266.5 h70
  text "D" at -416.5,198.5 h70
  text "D" at 14383.5,198.5 h70
  text "FILE NAME:" at 11343.5,106.5 h45
  text ".PCB_File_Name_No_Path" at 11393.5,-13.5 h70
  text "Texas Instruments (TI) and/or its licensors do not warrant the accuracy or completeness of this specification" at 6374,-175.34 h45
  text "ENGINEER:" at 11343.5,-183.5 h45
  text "LAYOUT BY:" at 12848.5,-183.5 h45
  text "or any information contained therein. TI and/or its licensors do not warrant that this design will meet" at 6329.01,-288 h45
  text ".PRJ_Engineer" at 11393.5,-338.49 h70
  text ".PCB_Layout" at 12899,-338.49 h70
  text "the specifications, will be suitable for your application or fit for any particular purpose, or will operate in" at 6329.01,-400.67 h45
  text ".Layer_Name" at 577,-428.49 h60
  text "ALTIUM DESIGNER VERSION:" at 12848.5,-493.5 h45
  text "an implementation. TI and/or its licensors do not warrant that the design is production worthy. You should" at 6329.01,-513.33 h45
  text "completely validate and test your design implementation to confirm the system functionality for your application." at 6374,-626 h45
  text ".print_Scale" at 11393.5,-626.83 h70
  text ".Application_BuildNumber" at 12899,-626.83 h70
  text "1" at 739.84,-833.5 h70
  text "2" at 3235.5,-833.5 h70
  text "3" at 5724.84,-833.5 h70
  text "4" at 8231.51,-833.5 h70
  text "5" at 10730.5,-833.5 h70
  text "6" at 13235.5,-833.5 h70
M10 Fab Notes:
  drawing of 189 lines, arcs and shapes, not listed
  text "DESIGN INFORMATION" at 12382.02,6786.17 h60
  text "MIN. TRACK WIDTH:" at 11737.46,6654.05 h60
  text "8" at 12833.7,6654.05 h60
  text "MIL" at 12988.46,6654.05 h60
  text "MIN. CLEARANCE:" at 11737.46,6529.92 h60
  text "0.2" at 12773.7,6529.93 h60
  text "mm" at 12988.46,6529.92 h60
  text "MIN. VIA PAD SIZE:" at 11737.46,6405.8 h60
  text "24" at 12803.71,6405.8 h60
  text "MIL" at 12988.46,6405.8 h60
  text "0.05mm (2MIL)" at 12432.46,6275.9 h60
  text "MINIMUM ANNULAR RING" at 11408.23,6267.67 h60
  text "EXTERNAL" at 13140.46,6267.67 h60
  text "PER" at 11608.23,6157.55 h60
  text "IPC-D-275 CLASS 2 LEVEL C" at 11828.23,6157.54 h60
  text "MIL, HOLES" at 13316.46,6057.07 h60
  text "+/-" at 12924,6048.48 h60
  text "+/-" at 13778,6048.48 h60
  text "REGISTRATION TOLERANCES:" at 11408.23,6047.42 h60
  text "METAL" at 12608,6047.42 h60
  text "5" at 13184.2,6047.42 h60
  text "3" at 14017.2,6047.42 h60
  text "MIL" at 14133.46,6047.42 h60
  text "HOLE SIZE TOLERANCE (UNLESS OTHERWISE SPECIFIED):" at 11408.23,5949.1 h60
  text "+/-" at 13778,5946.23 h60
  text "3" at 14017.2,5945.17 h60
  text "MIL" at 14133.46,5945.17 h60
  text "MATERIAL:" at 11333.46,5807.52 h60
  text "FR-4 High Tg" at 12319.9,5679 h60
  text "X" at 12175.46,5671.01 h60
  text "FR-408" at 11754.46,5666.49 h60
  text "OTHER" at 13242.46,5666.49 h60
  text "62 MIL (1.6mm) +/-10%" at 12074.56,5523.46 h60
  text "X" at 11954.46,5521.01 h60
  text "THICKNESS:" at 11408.23,5515.24 h60
  text "OTHER" at 13359.46,5515.24 h60
  text "TOLERANCE:" at 11408.23,5376.92 h60
  text "X" at 12256.46,5376.92 h60
  text "ANSI IPC-6012 TYPE 3 CLASS 2" at 12434.48,5376.92 h60
  text "OTHER +/-" at 12434.46,5232.73 h60
  text "BOW & TWIST:" at 11408.23,5087.54 h60
  text "X" at 12256.46,5087.54 h60
  text "ANSI IPC-6012 TYPE 3 CLASS 2" at 12434.48,5087.54 h60
  text "OTHER +/-" at 12434.46,4940.85 h60
  text "DRILLING:" at 11333.46,4810.23 h60
  text "NC_DRILL FILES" at 13094.46,4705.04 h60
  text "REFERENCE:" at 11408.23,4701.1 h60
  text "X" at 12065.46,4701.01 h60
  text "AS SHOWN" at 12243.46,4701.1 h60
  text "X" at 12966.46,4701.1 h60
  text "OTHER" at 13392.46,4558.85 h60
  text "PTH COPPER THICKNESS:" at 11407.91,4555.32 h60
  text "X" at 12547.14,4555.32 h60
  text "20-30 um" at 12675.14,4555.32 h60
  text "BOARD FINISH:" at 11333.46,4407.73 h60
  text "SILKSCREEN:" at 11488.68,4297.6 h60
  text "X" at 12446.46,4297.6 h60
  text "TOP" at 12563.46,4297.6 h60
  text "X" at 12956.46,4297.6 h60
  text "BOTTOM" at 13074.46,4297.6 h60
  text "SILKSCREEN COLOR:" at 11488.68,4142.41 h60
  text "X" at 12445.46,4142.41 h60
  text "WHITE" at 12563.46,4142.41 h60
  text "OTHER" at 13074.46,4142.41 h60
  text "X" at 12576.46,3998.96 h60
  text "GREEN" at 12694.46,3998.96 h60
  text "OTHER" at 13312.46,3998.96 h60
  text "SOLDER RESIST COLOR:" at 11488.68,3992.1 h60
  text "X" at 12576.46,3844.71 h60
  text "MATTE" at 12694.46,3844.71 h60
  text "SEMI-GLOSS" at 13312,3844.07 h60
  text "IMMERSION GOLD (ENIG)" at 12394.46,3671.94 h60
  text "ENEPIG" at 13732,3664.72 h60
  text "SURFACE FINISH:" at 11333.46,3663.72 h60
  text "X" at 12216.46,3663.72 h60
  text "IMM. TIN/SILVER OR EQUIV" at 11663,3526.4 h60
  text "OTHER" at 13094.46,3522.47 h60
  text "ARRAY/PANEL:" at 11333.46,3367.09 h60
  text "CUT AND TRIM PER M1 BOARD OUTLINE" at 12394.46,3358.87 h60
  text "N.C. ROUTE" at 12394.46,3222.9 h60
  text "X" at 13082.46,3222.9 h60
  text "V. SCORE" at 13260.46,3222.9 h60
  text "CERTIFICATION:" at 11333.46,3093.77 h60
  text "MATERIALS AND WORKMANSHIP FOR ALL PCBS" at 12058.46,3093.77 h60
  text "TO MEET OR EXCEED THE REQUIREMENTS OF:" at 12058.46,2999.71 h60
  text "X" at 11695.97,2871.08 h60
  text "ANSI IPC-A-600F CLASS ->" at 11823.96,2871.08 h60
  text "X" at 13471.97,2871.08 h60
  text "2" at 13581.96,2871.08 h60
  text "1" at 13266.96,2869.58 h60
  text "3" at 13935.96,2869.58 h60
  text "X" at 12507.97,2723.39 h60
  text "RoHS" at 12635.96,2723.39 h60
  text "OTHER" at 13280.36,2723.39 h60
  text "PER ORDER" at 13677.42,2723.39 h60
  text "ALL BOARDS MUST MEET OR EXCEED UL94-V0 REQUIREMENTS." at 11361,2569.57 h60
  text "PCB MUST BEAR THE UL94V-0 UL REGISTERED MATERIAL ID NUMBER" at 11361,2453.5 h60
  text "ADDITIONAL REQUIREMENTS:" at 11333.46,2284.08 h60
  text "MICROSECTION:" at 11408.23,2176.95 h60
  text "YES" at 12313.96,2176.95 h60
  text "REQUIRED" at 13175.46,2032.62 h60
  text "BARE BOARD ELEC. TEST:" at 11408.23,2029.76 h60
  text "NONE" at 12713.96,2029.76 h60
  text "X" at 13057.46,2029.76 h60
  text "PER ORDER" at 13767.46,2029.76 h60
  text "XX MIL VIAS REQUIRE NON-CONDUCTIVE FILL AND PLANARIZE" at 11576.38,1824.82 h59
  text "XX MIL VIAS REQUIRE CONDUCTIVE FILL AND PLANARIZE" at 11584.38,1720.84 h60
  text "OUTER XX MIL TRACES REQUIRE 50 OHM SINGLE-ENDED IMPEDANCE" at 11583.39,1557.46 h58
  text "LAYER 2 & 3 (INNER LAYERS) XX MIL WIDE, XX MIL SPACE / TRACES REQUIRE 100 OHM DIFFERENTIAL IMPEDANCE" at 11575.39,1321.74 h60
  text ".Layer_Name" at 577,-428.49 h60
M11 Gerber Information:
  lines w10: -292,-500.17 6308,-500.17 ; -292,-296.83 6310,-296.83 ; -292,-93.5 -292,-703.5 3713,-703.5 6310,-703.5 6310,-93.5 -291.5,-93.5 -291.5,-703.5 1284,-703.5 ; 2173,-703.5 2173,-93.5 ; 3440,-296.83 3440,-93.5 ; 4280,-296.83 4280,-93.5 ; 4902,-710 4902,-507.17
  text "ALL ARTWORK VIEWED FROM TOP SIDE" at -228.5,-225.67 h60
  text "BOARD #:" at 2248,-225.67 h60
  text ".PRJ_Number" at 2793.5,-225.67 h60
  text "REV:" at 3638,-225.67 h60
  text ".PCB_Rev" at 3929.5,-225.67 h60
  text "SVN REV:" at 4476,-225.67 h60
  text ".VersionControl_RevNumber" at 4982,-225.67 h60
  text "LAYER NAME =" at -228.5,-428.49 h60
  text "TID #:" at 2248,-429 h60
  text ".TID" at 2793.5,-429 h60
  text "PLOT NAME =" at -228.5,-634.34 h60
  text ".plot_File_Name" at 577,-634.34 h60
  text "GENERATED    :" at 2250,-634.34 h60
  text ".Print_Date" at 3119.5,-634.34 h60
  text ".Print_Time" at 3848.5,-634.34 h60
  text "TEXAS INSTRUMENTS" at 5113,-634.34 h60
M12 Stackup:
  drawing of 295 lines, arcs and shapes, not listed
  text "Layer" at 6509.09,7478.5 h60
  text "Name" at 6919,7478.5 h60
  text "Material" at 7848.74,7478.5 h60
  text "Thickness" at 8708.51,7478.5 h60
  text "Constant" at 9358.35,7478.5 h60
  text "Board Layer Stack" at 9928.21,7478.5 h60
  text "1" at 6509.09,7358.5 h60
  text "Top Overlay" at 6919,7358.5 h60
  text "2" at 6509.09,7238.5 h60
  text "Top Solder" at 6919,7238.5 h60
  text "Solder Resist" at 7848.74,7238.5 h60
  text "0.40mil" at 8708.51,7238.5 h60
  text "3.5" at 9358.35,7238.5 h60
  text "3" at 6509.09,7118.5 h60
  text "Top Layer" at 6919,7118.5 h60
  text "Copper" at 7848.74,7118.5 h60
  text "2.80mil" at 8708.51,7118.5 h60
  text "4" at 6509.09,6998.5 h60
  text "Dielectric 2" at 6919,6998.5 h60
  text "FR-4" at 7848.74,6998.5 h60
  text "10.00mil" at 8708.51,6998.5 h60
  text "4.8" at 9358.35,6998.5 h60
  text "5" at 6509.09,6878.5 h60
  text "GND Layer" at 6919,6878.5 h60
  text "Copper" at 7848.74,6878.5 h60
  text "1.40mil" at 8708.51,6878.5 h60
  text "6" at 6509.09,6758.5 h60
  text "Dielectric 1" at 6919,6758.5 h60
  text "FR-4" at 7848.74,6758.5 h60
  text "30.00mil" at 8708.51,6758.5 h60
  text "4.2" at 9358.35,6758.5 h60
  text "7" at 6509.09,6638.5 h60
  text "Power Layer" at 6919,6638.5 h60
  text "Copper" at 7848.74,6638.5 h60
  text "1.40mil" at 8708.51,6638.5 h60
  text "8" at 6509.09,6518.5 h60
  text "Dielectric 3" at 6919,6518.5 h60
  text "FR-4" at 7848.74,6518.5 h60
  text "10.00mil" at 8708.51,6518.5 h60
  text "4.8" at 9358.35,6518.5 h60
  text "9" at 6509.09,6398.5 h60
  text "Bottom Layer" at 6919,6398.5 h60
  text "Copper" at 7848.74,6398.5 h60
  text "2.80mil" at 8708.51,6398.5 h60
  text "10" at 6509.09,6278.5 h60
  text "Solder Side" at 6919,6278.5 h60
  text "Solder Resist" at 7848.74,6278.5 h60
  text "0.40mil" at 8708.51,6278.5 h60
  text "3.5" at 9358.35,6278.5 h60
  text "11" at 6509.09,6158.5 h60
  text "Bottom Overlay" at 6919,6158.5 h60
  text ".Layer_Name" at 577,-428.49 h60
M13 Component Bodies Top:
  text ".Layer_Name" at 577,-428.49 h60
M14 Component Bodies Bottom:
  text ".Layer_Name" at 577,-428.49 h60
M15 Courtyards Top:
  text ".Layer_Name" at 577,-428.49 h60
M16 Courtyards Bottom:
  text ".Layer_Name" at 577,-428.49 h60
Drill Drawing:
  circle w10: c5363.72,3865.96 r16.58
  circle w10: c5363.72,3865.96 r27.63
  circle w10: c5363.72,2871.4 r27.63
  lines w10: 5336.09,2968.09 5391.34,2968.09 5391.34,3023.35 5336.09,3023.35 5336.09,2968.09 ; 5336.09,3147.67 5391.34,3147.67 5363.72,3092.41 5336.09,3147.67 ; 5336.09,3216.73 5363.72,3230.55 5391.34,3216.73 5377.53,3244.36 5391.34,3271.99 5363.72,3258.17 5336.09,3271.99 5349.9,3244.36 5336.09,3216.73 ; 5336.09,3354.87 5349.9,3354.87 5349.9,3341.05 5377.53,3341.05 5377.53,3354.87 5391.34,3354.87 5391.34,3382.49 5377.53,3382.49 5377.53,3396.31 5349.9,3396.31 5349.9,3382.49 5336.09,3382.49 5336.09,3354.87 ; 5336.09,3479.19 5349.9,3479.19 5363.72,3465.37 5377.53,3479.19 5391.34,3479.19 5377.53,3493 5391.34,3506.81 5377.53,3506.81 5363.72,3520.63 5349.9,3506.81 5336.09,3506.81 5349.9,3493 5336.09,3479.19 ; 5336.09,3617.32 5363.72,3589.69 5391.34,3617.32 5363.72,3644.95 5336.09,3617.32 ; 5336.09,3714.01 5391.34,3714.01 5391.34,3769.27 5336.09,3769.27 5336.09,3714.01 ; 5336.09,3962.65 5336.09,3976.47 5349.9,3990.28 5336.09,4004.09 5336.09,4017.91 5349.9,4017.91 5363.72,4004.09 5377.53,4017.91 5391.34,4017.91 5391.34,4004.09 5377.53,3990.28 5391.34,3976.47 5391.34,3962.65 5377.53,3962.65 5363.72,3976.47 5349.9,3962.65 5336.09,3962.65 ; 5347.14,2979.14 5380.29,2979.14 5380.29,3012.3 5347.14,3012.3 5347.14,2979.14
  lines w12: 5286,2806.48 8517.49,2806.48 ; 5286,4049.68 8517.49,4049.68 ; 5623.86,2682.16 5623.86,4174 ; 5955.86,2682.16 5955.86,4174 ; 6592.43,2682.16 6592.43,4174 ; 6851.57,2682.16 6851.57,4174 ; 7226.72,2682.16 7226.72,4174 ; 7951.05,2682.16 7951.05,4174 ; 5286,2682.16 8517.49,2682.16 8517.49,4174 5286,4174 5286,2682.16
  text "Symbol" at 5360.59,4086.97 h72
  text "Quantity" at 5661.16,4086.97 h72
  text "Finished Hole Size" at 5993.16,4086.97 h72
  text "Plated" at 6629.72,4086.97 h72
  text "Hole Type" at 6888.86,4086.97 h72
  text "Drill Layer Pair" at 7264.02,4086.97 h72
  text "Hole Tolerance" at 7988.35,4086.97 h72
  text "258" at 5661.16,3962.65 h60
  text "7.87mil (0.200mm)" at 5993.16,3962.65 h60
  text "PTH" at 6629.72,3962.65 h60
  text "Round" at 6888.86,3962.65 h60
  text "Top Layer - Bottom Layer" at 7264.02,3962.65 h60
  text "759" at 5661.16,3838.33 h60
  text "10.00mil (0.254mm)" at 5993.16,3838.33 h60
  text "PTH" at 6629.72,3838.33 h60
  text "Round" at 6888.86,3838.33 h60
  text "Top Layer - Bottom Layer" at 7264.02,3838.33 h60
  text "3" at 5661.16,3714.01 h60
  text "27.56mil (0.700mm)" at 5993.16,3714.01 h60
  text "PTH" at 6629.72,3714.01 h60
  text "Round" at 6888.86,3714.01 h60
  text "Top Layer - Bottom Layer" at 7264.02,3714.01 h60
  text "16" at 5661.16,3589.69 h60
  text "33.47mil (0.850mm)" at 5993.16,3589.69 h60
  text "PTH" at 6629.72,3589.69 h60
  text "Round" at 6888.86,3589.69 h60
  text "Top Layer - Bottom Layer" at 7264.02,3589.69 h60
  text "39" at 5661.16,3465.37 h60
  text "40.00mil (1.016mm)" at 5993.16,3465.37 h60
  text "PTH" at 6629.72,3465.37 h60
  text "Round" at 6888.86,3465.37 h60
  text "Top Layer - Bottom Layer" at 7264.02,3465.37 h60
  text "46" at 5661.16,3341.05 h60
  text "40.16mil (1.020mm)" at 5993.16,3341.05 h60
  text "PTH" at 6629.72,3341.05 h60
  text "Round" at 6888.86,3341.05 h60
  text "Top Layer - Bottom Layer" at 7264.02,3341.05 h60
  text "5" at 5661.16,3216.73 h60
  text "47.24mil (1.200mm)" at 5993.16,3216.73 h60
  text "PTH" at 6629.72,3216.73 h60
  text "Round" at 6888.86,3216.73 h60
  text "Top Layer - Bottom Layer" at 7264.02,3216.73 h60
  text "6" at 5661.16,3092.41 h60
  text "51.18mil (1.300mm)" at 5993.16,3092.41 h60
  text "PTH" at 6629.72,3092.41 h60
  text "Round" at 6888.86,3092.41 h60
  text "Top Layer - Bottom Layer" at 7264.02,3092.41 h60
  text "5" at 5661.16,2968.09 h60
  text "51.18mil (1.300mm)" at 5993.16,2968.09 h60
  text "PTH" at 6629.72,2968.09 h60
  text "Round" at 6888.86,2968.09 h60
  text "Top Layer - Bottom Layer" at 7264.02,2968.09 h60
  text "+/-3.94mil" at 7988.35,2968.09 h60
  text "4" at 5661.16,2843.77 h60
  text "125.98mil (3.200mm)" at 5993.16,2843.77 h60
  text "PTH" at 6629.72,2843.77 h60
  text "Round" at 6888.86,2843.77 h60
  text "Top Layer - Bottom Layer" at 7264.02,2843.77 h60
  text "1141 Total" at 5661.16,2719.45 h60
  text ".Layer_Name" at 577,-428.49 h60
M17 Embedded Cavity:
  text ".Layer_Name" at 577,-428.49 h60
M18 Embedded Assembly:
  text ".Layer_Name" at 577,-428.49 h60
M19 Embedded Keepout:
  text ".Layer_Name" at 577,-428.49 h60

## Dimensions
0,30 to 1000,30 on M2 Board Dimensions
0,430 to 0,5180 on M2 Board Dimensions
0,430 to 3650,0 on M2 Board Dimensions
